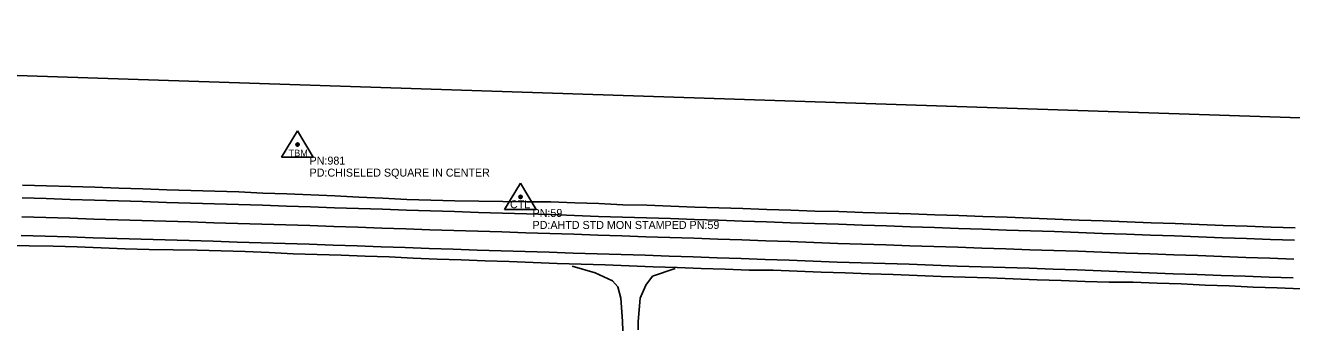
# Model space of a CAD drawing. Extents: x 976456 to 985170, y 1525951 to 1527080.
# Drawn here: x 980022 to 980813, y 1526358 to 1526549 of the extents above; entities that cross this region are included whole.
import ezdxf

# ---------------------------------------------------------------- set-up
doc = ezdxf.new("R2010")
doc.units = 0
for name, color, linetype in [('S_DRIVEWAY', 7, 'Continuous'), ('S_EDGE_PAVEMENT', 7, 'Continuous'), ('S_FIBER_OPTIC_CABLE', 7, 'Continuous'), ('S_PAVEMENT_CROWN', 7, 'Continuous'), ('S_PRIMARY_CTL', 7, 'Continuous'), ('S_PRIMARY_CTL_ANNOT', 7, 'Continuous'), ('S_SHOULDER', 7, 'Continuous')]:
    doc.layers.add(name, color=color, linetype=linetype)

msp = doc.modelspace()

# ---------------------------------------------------------------- linework, layer by layer
at = {"layer": 'S_DRIVEWAY'}
for points in [[(980363.59, 1526398.14), (980378.05, 1526393.98), (980388.95, 1526389.02), (980392.22, 1526385.28), (980394.16, 1526378.02), (980395.16, 1526363.69), (980395.41, 1526357.75)], [(980427.9, 1526396.65), (980413.94, 1526391.89), (980409.62, 1526386.17), (980406.22, 1526378.17), (980404.83, 1526363.6), (980404.81, 1526358.28)]]:
    msp.add_lwpolyline(points, dxfattribs=at)
at = {"layer": 'S_EDGE_PAVEMENT'}
for points in [[(980020.22, 1526440.83), (980035.21, 1526440.4), (980050.24, 1526439.86), (980065.24, 1526439.43), (980080.23, 1526438.87), (980080.23, 1526438.87), (980095.22, 1526438.48), (980110.21, 1526438.01), (980125.21, 1526437.51), (980140.2, 1526437.09), (980155.2, 1526436.71), (980155.2, 1526436.71), (980170.19, 1526436.18), (980185.18, 1526435.7), (980185.18, 1526435.7), (980200.18, 1526435.22), (980215.16, 1526434.61), (980230.16, 1526434.17), (980245.15, 1526433.75), (980260.14, 1526433.21), (980275.13, 1526432.73), (980290.12, 1526432.21), (980305.11, 1526431.63), (980320.11, 1526431.16), (980335.1, 1526430.8), (980350.12, 1526430.33), (980365.11, 1526429.77), (980380.1, 1526429.26), (980395.1, 1526428.76), (980410.09, 1526428.38), (980425.08, 1526427.84), (980440.07, 1526427.33), (980455.07, 1526426.83), (980470.06, 1526426.35), (980485.05, 1526425.83), (980500.04, 1526425.31), (980500.04, 1526425.31), (980515.03, 1526424.8), (980515.03, 1526424.8), (980530.02, 1526424.29), (980545.01, 1526423.77), (980545.01, 1526423.77), (980560.01, 1526423.26), (980575, 1526422.73), (980575, 1526422.73), (980589.99, 1526422.23), (980604.98, 1526421.77), (980619.97, 1526421.26), (980619.97, 1526421.26), (980634.98, 1526420.73), (980649.97, 1526420.2), (980664.96, 1526419.74), (980679.95, 1526419.14), (980694.94, 1526418.61), (980709.93, 1526418.08), (980724.92, 1526417.55), (980739.91, 1526417.02), (980739.91, 1526417.02), (980754.9, 1526416.49), (980769.9, 1526415.93), (980769.9, 1526415.93), (980784.89, 1526415.4), (980799.88, 1526414.86), (980814.87, 1526414.33)], [(980019.54, 1526417.34), (980034.54, 1526416.85), (980049.49, 1526416.36), (980064.49, 1526415.92), (980064.49, 1526415.92), (980079.48, 1526415.42), (980094.47, 1526415.01), (980109.47, 1526414.6), (980109.47, 1526414.6), (980124.46, 1526414.14), (980139.45, 1526413.69), (980154.45, 1526413.22), (980169.44, 1526412.78), (980184.43, 1526412.29), (980199.42, 1526411.77), (980214.41, 1526411.26), (980229.4, 1526410.74), (980244.39, 1526410.22), (980244.39, 1526410.22), (980259.39, 1526409.72), (980259.39, 1526409.72), (980274.38, 1526409.23), (980289.37, 1526408.71), (980304.36, 1526408.21), (980319.35, 1526407.75), (980319.35, 1526407.75), (980334.35, 1526407.29), (980349.31, 1526406.82), (980364.31, 1526406.34), (980379.3, 1526405.88), (980379.3, 1526405.88), (980394.29, 1526405.36), (980394.29, 1526405.36), (980409.28, 1526404.92), (980424.28, 1526404.42), (980424.28, 1526404.42), (980439.27, 1526403.9), (980454.26, 1526403.38), (980454.26, 1526403.38), (980469.25, 1526402.82), (980484.24, 1526402.31), (980499.23, 1526401.81), (980514.22, 1526401.22), (980514.22, 1526401.22), (980529.21, 1526400.66), (980544.2, 1526400.18), (980559.2, 1526399.74), (980574.19, 1526399.26), (980574.19, 1526399.26), (980589.18, 1526398.72), (980604.17, 1526398.18), (980604.17, 1526398.18), (980619.16, 1526397.77), (980619.16, 1526397.77), (980634.15, 1526397.3), (980634.15, 1526397.3), (980649.14, 1526396.81), (980649.14, 1526396.81), (980664.13, 1526396.34), (980679.12, 1526395.78), (980679.12, 1526395.78), (980694.11, 1526395.2), (980709.1, 1526394.63), (980709.1, 1526394.63), (980724.08, 1526393.99), (980724.08, 1526393.99), (980739.07, 1526393.4), (980754.07, 1526392.87), (980769.05, 1526392.34), (980769.05, 1526392.34), (980784.04, 1526391.82), (980799.04, 1526391.32), (980814.03, 1526390.79)]]:
    msp.add_lwpolyline(points, dxfattribs=at)
at = {"layer": 'S_FIBER_OPTIC_CABLE'}
msp.add_line((982227.16, 1526444.43), (979068.74, 1526548.75), dxfattribs=at)
at = {"layer": 'S_PAVEMENT_CROWN'}
msp.add_lwpolyline([(980019.88, 1526429.03), (980034.87, 1526428.52), (980034.87, 1526428.52), (980049.86, 1526428.04), (980049.86, 1526428.04), (980064.86, 1526427.57), (980079.85, 1526427.09), (980094.84, 1526426.61), (980109.84, 1526426.27), (980124.83, 1526425.79), (980124.83, 1526425.79), (980139.82, 1526425.28), (980139.82, 1526425.28), (980154.82, 1526424.86), (980169.81, 1526424.38), (980169.81, 1526424.38), (980184.8, 1526423.9), (980199.8, 1526423.45), (980199.8, 1526423.45), (980214.79, 1526422.97), (980229.78, 1526422.42), (980244.77, 1526421.94), (980244.77, 1526421.94), (980259.76, 1526421.44), (980259.76, 1526421.44), (980274.75, 1526420.93), (980274.75, 1526420.93), (980289.74, 1526420.39), (980304.74, 1526420.02), (980304.74, 1526420.02), (980319.73, 1526419.51), (980319.73, 1526419.51), (980334.72, 1526419.03), (980349.72, 1526418.55), (980349.72, 1526418.55), (980364.71, 1526418.03), (980379.7, 1526417.5), (980379.7, 1526417.5), (980394.69, 1526417.02), (980409.68, 1526416.51), (980424.68, 1526416.09), (980424.68, 1526416.09), (980439.67, 1526415.57), (980439.67, 1526415.57), (980454.66, 1526415.05), (980454.66, 1526415.05), (980469.65, 1526414.51), (980484.64, 1526413.99), (980484.64, 1526413.99), (980499.63, 1526413.48), (980514.62, 1526412.88), (980514.62, 1526412.88), (980529.61, 1526412.36), (980544.61, 1526411.92), (980559.6, 1526411.38), (980559.6, 1526411.38), (980574.59, 1526410.87), (980589.58, 1526410.41), (980604.57, 1526409.9), (980604.57, 1526409.9), (980619.57, 1526409.45), (980619.57, 1526409.45), (980634.56, 1526408.93), (980649.55, 1526408.4), (980649.55, 1526408.4), (980664.54, 1526407.97), (980664.54, 1526407.97), (980679.53, 1526407.44), (980679.53, 1526407.44), (980694.52, 1526406.86), (980694.52, 1526406.86), (980709.51, 1526406.32), (980724.5, 1526405.81), (980724.5, 1526405.81), (980739.49, 1526405.28), (980754.48, 1526404.69), (980754.48, 1526404.69), (980769.47, 1526404.15), (980784.46, 1526403.6), (980799.46, 1526403.07), (980799.46, 1526403.07), (980814.45, 1526402.54)], dxfattribs=at)
at = {"layer": 'S_PRIMARY_CTL'}
for p, q in [((980192.17, 1526482.82), (980182.14, 1526466.3)), ((980192.17, 1526482.82), (980201.99, 1526466.3)), ((980182.14, 1526466.3), (980201.99, 1526466.3)), ((980331.44, 1526450.09), (980321.4, 1526433.58)), ((980331.44, 1526450.09), (980341.26, 1526433.58)), ((980321.4, 1526433.58), (980341.26, 1526433.58))]:
    msp.add_line(p, q, dxfattribs=at)
for centre, radius in [((980192.17, 1526474.12), 1.04), ((980192.17, 1526474.12), 0.609), ((980192.17, 1526474.12), 0.344), ((980331.44, 1526441.39), 1.04), ((980331.44, 1526441.39), 0.609), ((980331.44, 1526441.39), 0.344)]:
    msp.add_circle(centre, radius, dxfattribs=at)
at = {"layer": 'S_SHOULDER'}
for points in [[(980020.45, 1526448.84), (980035.44, 1526448.3), (980050.5, 1526447.86), (980065.49, 1526447.42), (980080.48, 1526446.88), (980095.48, 1526446.5), (980110.47, 1526445.92), (980125.46, 1526445.38), (980140.46, 1526444.96), (980155.45, 1526444.53), (980170.44, 1526443.85), (980185.43, 1526443.37), (980200.42, 1526442.76), (980215.41, 1526442.15), (980230.39, 1526441.34), (980245.38, 1526440.67), (980260.36, 1526439.82), (980275.35, 1526439.4), (980290.34, 1526438.87), (980305.35, 1526438.86), (980320.35, 1526438.53), (980335.35, 1526438.39), (980350.4, 1526438.27), (980365.39, 1526437.71), (980380.38, 1526437.2), (980395.37, 1526436.57), (980410.37, 1526436.18), (980425.36, 1526435.64), (980440.35, 1526435.1), (980455.34, 1526434.6), (980470.33, 1526434.12), (980485.32, 1526433.55), (980500.31, 1526433.06), (980515.3, 1526432.54), (980530.3, 1526432.25), (980545.29, 1526431.73), (980560.29, 1526431.35), (980575.28, 1526430.74), (980590.27, 1526430.24), (980605.26, 1526429.78), (980620.25, 1526429.27), (980635.26, 1526428.75), (980650.26, 1526428.22), (980665.24, 1526427.6), (980680.23, 1526426.92), (980695.22, 1526426.39), (980710.21, 1526425.86), (980725.2, 1526425.28), (980740.19, 1526424.77), (980755.18, 1526424.23), (980770.17, 1526423.62), (980785.16, 1526423.08), (980800.15, 1526422.55), (980815.14, 1526422.02)], [(980009.49, 1526411.07), (980024.49, 1526410.89), (980039.49, 1526410.65), (980054.43, 1526410.18), (980069.42, 1526409.58), (980084.41, 1526409.01), (980099.4, 1526408.52), (980114.4, 1526408.29), (980129.4, 1526408.09), (980144.4, 1526407.65), (980159.39, 1526407.25), (980174.38, 1526406.59), (980189.36, 1526405.84), (980204.35, 1526405.31), (980219.34, 1526404.92), (980234.33, 1526404.39), (980249.33, 1526403.88), (980264.31, 1526403.2), (980279.3, 1526402.42), (980294.29, 1526401.99), (980309.28, 1526401.51), (980324.28, 1526401.07), (980339.26, 1526400.44), (980354.21, 1526399.72), (980369.2, 1526399.26), (980384.2, 1526398.86), (980399.18, 1526398.28), (980414.17, 1526397.72), (980429.17, 1526397.23), (980444.16, 1526396.72), (980459.15, 1526396.21), (980474.14, 1526395.66), (980489.14, 1526395.57), (980504.13, 1526394.95), (980519.12, 1526394.44), (980534.11, 1526393.9), (980549.1, 1526393.38), (980564.1, 1526392.86), (980579.08, 1526392.23), (980594.07, 1526391.66), (980609.06, 1526391.14), (980624.06, 1526390.86), (980639.03, 1526390.27), (980654.02, 1526389.58), (980669.01, 1526389.09), (980684, 1526388.43), (980699, 1526388.2), (980714.01, 1526388.12), (980728.99, 1526387.43), (980743.99, 1526387.1), (980758.97, 1526386.26), (980773.96, 1526385.77), (980788.94, 1526385.07), (980803.93, 1526384.47), (980818.92, 1526383.93)]]:
    msp.add_lwpolyline(points, dxfattribs=at)

# ---------------------------------------------------------------- texts
at = {"layer": 'S_PRIMARY_CTL'}
for s, height, p in [('TBM', 4.287, (980186.52, 1526466.73)), ('CTL', 5, (980324.85, 1526434.32))]:
    msp.add_text(s, height=height, rotation=360, dxfattribs=at).set_placement(p)
at = {"layer": 'S_PRIMARY_CTL_ANNOT'}
for s, p in [('PN:981', (980199.67, 1526461.62)), ('PD:CHISELED SQUARE IN CENTER', (980199.67, 1526454.12)), ('PN:59', (980338.94, 1526428.89)), ('PD:AHTD STD MON STAMPED PN:59', (980338.94, 1526421.39))]:
    msp.add_text(s, height=5, dxfattribs=at).set_placement(p)

doc.saveas('drawing.dxf')
